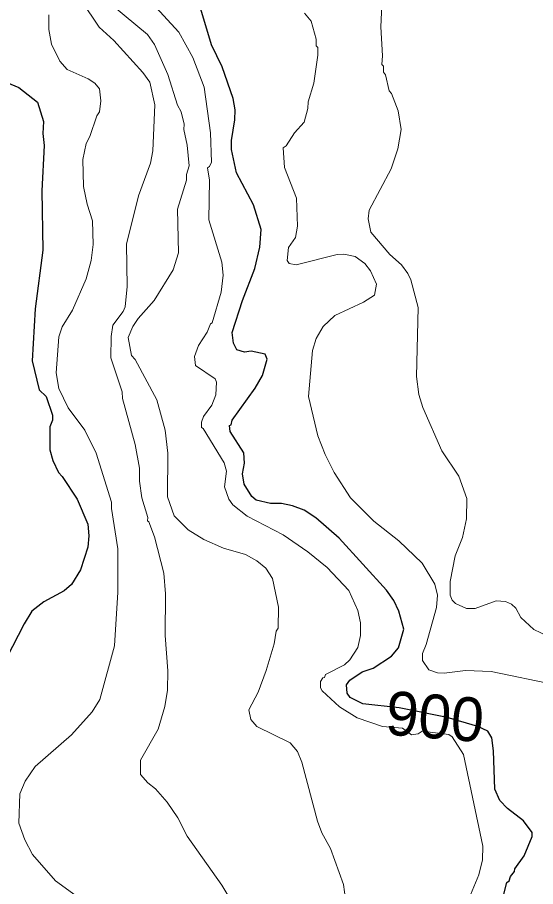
# Model space of a CAD drawing. Extents: x 598.3 to 623.2, y 6902.2 to 6930.1.
# Drawn here: x 601.918 to 602.863, y 6927.55 to 6929.137 of the extents above; entities that cross this region are included whole.
import ezdxf
from ezdxf.enums import TextEntityAlignment as Align

# ---------------------------------------------------------------- set-up
doc = ezdxf.new("R2010")
doc.units = 0
doc.header["$LTSCALE"] = 0.032
doc.layers.add('1', color=7, linetype='Continuous', lineweight=25)
doc.layers.add('2', color=7, linetype='Continuous', lineweight=13)
doc.layers.add('61', color=7, linetype='Continuous')

msp = doc.modelspace()

# ---------------------------------------------------------------- linework, layer by layer
at = {"layer": '1'}
for points in [[(602.3695, 6928.5217), (602.3445, 6928.5271), (602.3322, 6928.5257), (602.3184, 6928.5299), (602.312, 6928.542), (602.3097, 6928.5615), (602.3283, 6928.6197), (602.351, 6928.678), (602.3599, 6928.7169), (602.3622, 6928.7495), (602.3484, 6928.7946), (602.3177, 6928.8529), (602.3086, 6928.8953), (602.3081, 6928.9116), (602.3145, 6928.9494), (602.3153, 6928.9678), (602.3113, 6928.9883), (602.2913, 6929.0462), (602.2722, 6929.0864), (602.2488, 6929.1637)], [(601.8987, 6929.0176), (601.9203, 6929.0088), (601.9543, 6928.9821), (601.9656, 6928.9465), (601.9641, 6928.9247), (601.9664, 6928.903), (601.9623, 6928.8202), (601.964, 6928.7114), (601.9502, 6928.6049), (601.9446, 6928.51), (601.9576, 6928.4569), (601.9705, 6928.4444), (601.9818, 6928.4107), (601.9818, 6928.4017), (601.977, 6928.3892), (601.977, 6928.3472), (601.9822, 6928.3278), (601.993, 6928.3057), (601.9998, 6928.2987), (602.027, 6928.2571), (602.0465, 6928.2115), (602.0482, 6928.1901), (602.0465, 6928.1694), (602.0331, 6928.1281), (602.0166, 6928.1016), (602.003, 6928.0902), (601.9659, 6928.07), (601.9444, 6928.0526), (601.9299, 6928.0299), (601.8978, 6927.9673)], [(602.8046, 6927.5338), (602.8105, 6927.5576), (602.8148, 6927.5609), (602.8173, 6927.5687), (602.8243, 6927.5774), (602.8249, 6927.5828), (602.8425, 6927.6063), (602.8568, 6927.6416), (602.8568, 6927.6487), (602.8412, 6927.6701), (602.8121, 6927.6928), (602.798, 6927.707), (602.7888, 6927.7277), (602.7865, 6927.7979), (602.7833, 6927.8216), (602.7758, 6927.834), (602.7576, 6927.8426), (602.7015, 6927.8588), (602.614, 6927.8761), (602.5478, 6927.8838), (602.5246, 6927.8954), (602.5193, 6927.9033), (602.5181, 6927.9182), (602.524, 6927.9271), (602.5469, 6927.9419), (602.5666, 6927.9486), (602.6, 6927.9709), (602.6132, 6927.9857), (602.6228, 6928.0199), (602.6139, 6928.0531), (602.6045, 6928.072), (602.591, 6928.0911), (602.5049, 6928.1861), (602.4621, 6928.2234), (602.4407, 6928.2373), (602.4197, 6928.2452), (602.3998, 6928.2495), (602.3798, 6928.2496), (602.3536, 6928.2552), (602.3454, 6928.2623), (602.3315, 6928.2846), (602.3283, 6928.3034), (602.3323, 6928.3232), (602.3308, 6928.3419), (602.3061, 6928.3809), (602.3049, 6928.3917), (602.3079, 6928.393), (602.3099, 6928.4013), (602.3517, 6928.4599), (602.3651, 6928.4828), (602.3735, 6928.5129), (602.3695, 6928.5217)]]:
    msp.add_lwpolyline(points, dxfattribs=at)
at = {"layer": '2'}
for points in [[(602.3233, 6927.4978), (602.2909, 6927.5528), (602.2276, 6927.6423), (602.2102, 6927.6754), (602.1908, 6927.7045), (602.1699, 6927.7288), (602.1558, 6927.7396), (602.1427, 6927.7549), (602.1421, 6927.7808), (602.1744, 6927.8375), (602.1865, 6927.8791), (602.1914, 6927.9085), (602.1922, 6927.9438), (602.1874, 6928.0085), (602.1882, 6928.0842), (602.1851, 6928.1219), (602.168, 6928.1886), (602.1575, 6928.2159), (602.1551, 6928.2174), (602.1557, 6928.2235), (602.1446, 6928.2598), (602.1405, 6928.2903), (602.1404, 6928.3141), (602.1324, 6928.357), (602.1098, 6928.4412), (602.1088, 6928.4533), (602.0883, 6928.5149), (602.0886, 6928.5541), (602.0921, 6928.5749), (602.111, 6928.5998), (602.1145, 6928.6085), (602.1179, 6928.6453), (602.117, 6928.7229), (602.1385, 6928.8111), (602.1607, 6928.8705), (602.1647, 6928.8929), (602.1688, 6928.9772), (602.1596, 6929.0186), (602.1465, 6929.0361), (602.0937, 6929.0944), (602.0669, 6929.1188), (602.0011, 6929.2171)], [(602.0699, 6929.1766), (602.1549, 6929.1053), (602.1678, 6929.0868), (602.1921, 6929.0326), (602.2097, 6928.9766), (602.2166, 6928.9641), (602.2222, 6928.9417), (602.2215, 6928.9319), (602.2278, 6928.9031), (602.2312, 6928.8656), (602.2263, 6928.8496), (602.2262, 6928.8396), (602.2101, 6928.7865), (602.2117, 6928.707), (602.2017, 6928.6755), (602.1673, 6928.6197), (602.138, 6928.5872), (602.1282, 6928.5723), (602.1202, 6928.5525), (602.1261, 6928.5192), (602.1326, 6928.5121), (602.1719, 6928.4384), (602.1874, 6928.3831), (602.1922, 6928.3413), (602.1915, 6928.2615), (602.204, 6928.227), (602.2293, 6928.2011), (602.2577, 6928.1836), (602.2938, 6928.1679), (602.3339, 6928.156), (602.3545, 6928.1449), (602.3713, 6928.1311), (602.3831, 6928.1122), (602.3939, 6928.0604), (602.3938, 6928.0215), (602.3898, 6928.0164), (602.3865, 6927.9932), (602.3719, 6927.9443), (602.3572, 6927.905), (602.3397, 6927.8728), (602.3438, 6927.8551), (602.3547, 6927.8422), (602.4156, 6927.8123), (602.4289, 6927.7965), (602.4368, 6927.7774), (602.465, 6927.6698), (602.4732, 6927.6481), (602.4889, 6927.6197), (602.5129, 6927.554), (602.5161, 6927.5273)], [(602.1638, 6929.1628), (602.2121, 6929.1096), (602.2381, 6929.0636), (602.2587, 6929.0094), (602.2699, 6928.9257), (602.2716, 6928.8721), (602.2684, 6928.8642), (602.2645, 6928.8622), (602.2684, 6928.8392), (602.2668, 6928.7668), (602.2909, 6928.6897), (602.2934, 6928.6662), (602.2893, 6928.6351), (602.2732, 6928.5792), (602.27, 6928.5773), (602.264, 6928.5621), (602.2484, 6928.5377), (602.2409, 6928.5178), (602.2425, 6928.5014), (602.2787, 6928.4771), (602.2813, 6928.4705), (602.2797, 6928.4478), (602.2727, 6928.429), (602.2576, 6928.4084), (602.2539, 6928.3976), (602.2539, 6928.3882), (602.257, 6928.3862), (602.2949, 6928.3235), (602.2992, 6928.3086), (602.2959, 6928.2796), (602.3037, 6928.2574), (602.3106, 6928.247), (602.3369, 6928.2264), (602.4025, 6928.1922), (602.4475, 6928.1611), (602.4826, 6928.1325)], [(602.5824, 6929.1586), (602.5808, 6929.1192), (602.584, 6929.0666), (602.5825, 6929.0504), (602.5856, 6929.0474), (602.5857, 6929.0366), (602.589, 6929.0318), (602.5961, 6929.0028), (602.6002, 6928.9974), (602.6124, 6928.9659), (602.618, 6928.9319), (602.6115, 6928.8964), (602.5995, 6928.8604), (602.5597, 6928.7844), (602.5574, 6928.7687), (602.5628, 6928.7446), (602.5972, 6928.7035), (602.6182, 6928.6848), (602.6301, 6928.669), (602.6354, 6928.6574), (602.6488, 6928.6071), (602.6456, 6928.4809), (602.65, 6928.4481), (602.6572, 6928.4247), (602.6919, 6928.3457), (602.723, 6928.2995), (602.7378, 6928.2584), (602.7371, 6928.2215), (602.7298, 6928.1875), (602.7166, 6928.1539), (602.7072, 6928.1068), (602.7073, 6928.0822), (602.7109, 6928.0728), (602.7169, 6928.0666), (602.7371, 6928.0575), (602.7527, 6928.0577), (602.7913, 6928.0714), (602.8083, 6928.0706), (602.8194, 6928.0657), (602.8269, 6928.0583), (602.8362, 6928.0411), (602.8596, 6928.0195), (602.8852, 6928.0075)], [(601.9753, 6929.1411), (601.9749, 6929.1143), (601.9801, 6929.0876), (601.9954, 6929.0569), (602.0086, 6929.0413), (602.0472, 6929.0247), (602.0593, 6929.0163), (602.0675, 6929.0063), (602.07, 6928.9843), (602.0677, 6928.9641), (602.0626, 6928.9571), (602.0499, 6928.9193), (602.043, 6928.9066), (602.037, 6928.8773), (602.0385, 6928.8281), (602.045, 6928.7957), (602.0548, 6928.7653), (602.0562, 6928.722), (602.0523, 6928.6929), (602.0431, 6928.6593), (602.0185, 6928.6023), (601.9994, 6928.572), (601.9932, 6928.5534), (601.9883, 6928.4877), (601.9937, 6928.4593), (602.0107, 6928.4239), (602.0408, 6928.3831), (602.0618, 6928.3413), (602.0898, 6928.252), (602.0895, 6928.2404), (602.1008, 6928.1667), (602.1009, 6928.0874), (602.0951, 6927.9898), (602.068, 6927.8919), (602.054, 6927.8693), (602.0163, 6927.8274), (601.9503, 6927.7696), (601.9319, 6927.7426), (601.922, 6927.7192), (601.9203, 6927.6657), (601.9316, 6927.6355)], [(602.8991, 6927.9181), (602.7819, 6927.9427), (602.7351, 6927.9443), (602.6964, 6927.9394), (602.6842, 6927.9404), (602.6685, 6927.9457), (602.657, 6927.9625), (602.6569, 6927.9753), (602.6636, 6927.9919), (602.6821, 6928.0596), (602.6844, 6928.0819), (602.6793, 6928.102), (602.6561, 6928.1402), (602.6135, 6928.1814), (602.5677, 6928.2173), (602.5253, 6928.2595), (602.4957, 6928.3057), (602.4791, 6928.3389), (602.466, 6928.3728), (602.4489, 6928.4444), (602.4562, 6928.5288), (602.4629, 6928.5504), (602.4755, 6928.5723), (602.4966, 6928.5927), (602.549, 6928.6165), (602.5695, 6928.6296), (602.5727, 6928.6499), (602.5617, 6928.674), (602.5517, 6928.6875), (602.5341, 6928.7002), (602.5131, 6928.7044), (602.5013, 6928.7036), (602.4264, 6928.6851), (602.4133, 6928.6876), (602.4097, 6928.6931), (602.4125, 6928.7163), (602.4254, 6928.7347), (602.4286, 6928.7555), (602.4267, 6928.8066), (602.4051, 6928.8627), (602.4028, 6928.8985), (602.4078, 6928.9024), (602.4231, 6928.9256), (602.4412, 6928.9452), (602.4479, 6928.9702), (602.4481, 6928.9824), (602.4587, 6929.0167), (602.4658, 6929.0674), (602.4658, 6929.0814), (602.4627, 6929.0844), (602.4626, 6929.097), (602.4537, 6929.1294), (602.4415, 6929.1444)], [(602.4826, 6928.1325), (602.5227, 6928.0906), (602.5388, 6928.0542), (602.5436, 6928.0315), (602.5436, 6928.0085), (602.5388, 6927.9867), (602.5243, 6927.9641), (602.5146, 6927.955), (602.48, 6927.937), (602.4779, 6927.9315), (602.4748, 6927.931), (602.4708, 6927.9246), (602.4708, 6927.9132), (602.4739, 6927.9074), (602.5056, 6927.8783), (602.5378, 6927.8582), (602.5839, 6927.8424), (602.6204, 6927.8391), (602.637, 6927.827), (602.6487, 6927.8287), (602.6563, 6927.8341), (602.7051, 6927.828), (602.7106, 6927.8235), (602.7314, 6927.7915), (602.767, 6927.6238), (602.7664, 6927.599), (602.7595, 6927.5714), (602.7381, 6927.5208)], [(601.9316, 6927.6355), (601.9455, 6927.609), (601.9876, 6927.5606), (602.0318, 6927.5284)]]:
    msp.add_lwpolyline(points, dxfattribs=at)

# ---------------------------------------------------------------- texts
at = {"layer": '61'}
msp.add_text('900', height=0.08, rotation=355.292, dxfattribs=at).set_placement((602.6762, 6927.8207), align=Align.CENTER)

doc.saveas('drawing.dxf')
